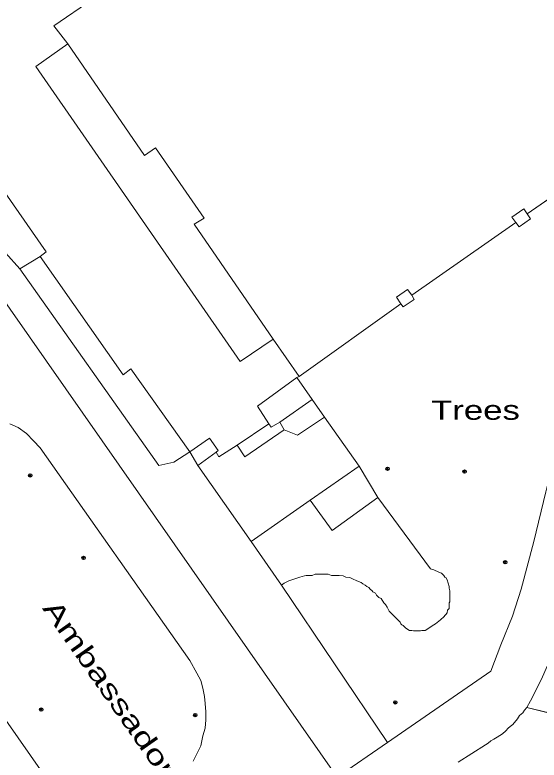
# Model space of a CAD drawing. Extents: x 528790 to 529292, y 179350 to 179856.
# Drawn here: x 529081.7 to 529129.4, y 179559 to 179626.8 of the extents above; entities that cross this region are included whole.
import ezdxf

# ---------------------------------------------------------------- set-up
doc = ezdxf.new("R2010")
doc.units = 0
doc.header["$LTSCALE"] = 0.6
doc.header["$PDMODE"] = 32
doc.header["$PDSIZE"] = 0.3
doc.layers.add('1', color=7, linetype='Continuous', lineweight=13)
doc.layers.add('2', color=7, linetype='Continuous', lineweight=13)
doc.layers.add('3', color=7, linetype='Continuous')
doc.layers.add('5', color=7, linetype='Continuous')

msp = doc.modelspace()

# ---------------------------------------------------------------- linework, layer by layer
at = {"layer": '1'}
for points in [[(529079.55, 179612.4), (529084.55, 179605.25), (529084, 179604.8), (529091.55, 179594.05), (529092.25, 179594.6), (529097.6, 179587.05), (529099.4, 179588.3), (529100.2, 179587.15), (529100, 179587), (529100.25, 179586.6), (529101.9, 179587.65), (529104.8, 179589.6), (529103.75, 179591.2), (529107.35, 179593.8), (529107.55, 179593.9), (529105.2, 179597.3), (529102.2, 179595.25), (529083.6, 179622.1), (529086.5, 179624.15), (529085.25, 179625.8), (529088.8, 179628.25)], [(529088.8, 179628.25), (529085.25, 179625.8), (529086.5, 179624.15), (529093.5, 179614), (529094.5, 179614.7), (529098.9, 179608.3), (529098, 179607.75), (529105.2, 179597.3), (529107.55, 179593.9), (529116.8, 179600.5), (529116.4, 179601.1)], [(529137.65, 179615.2), (529128.3, 179608.7), (529128.6, 179608.25), (529127.55, 179607.5), (529127.25, 179607.9), (529117.8, 179601.3), (529118, 179600.9), (529117, 179600.25), (529116.8, 179600.5), (529107.55, 179593.9), (529107.35, 179593.8), (529108.75, 179591.8), (529109.85, 179590.2), (529113, 179585.75), (529114.7, 179582.9), (529119.5, 179576.4), (529119.8, 179576.3), (529120.25, 179576.1), (529120.5, 179576), (529120.7, 179575.8), (529120.8, 179575.65), (529120.9, 179575.6), (529121, 179575.4), (529121.2, 179574.8), (529121.2, 179574.65), (529121.25, 179574.4), (529121.25, 179573.4), (529121.2, 179573.3), (529121.2, 179572.8), (529121.05, 179572.65), (529121, 179572.4), (529120.9, 179572.25), (529120.8, 179572.15), (529120.75, 179572.05), (529120.4, 179571.75), (529120.25, 179571.65), (529119.95, 179571.4), (529119.8, 179571.3), (529119, 179570.8), (529118.7, 179570.8), (529118.6, 179570.75), (529117.95, 179570.75), (529117.8, 179570.8), (529117.6, 179570.8), (529117.25, 179571), (529117, 179571.25), (529116.9, 179571.3), (529116.8, 179571.4), (529116.75, 179571.55), (529115.75, 179572.55), (529115.55, 179572.9), (529115.4, 179573.15), (529115.25, 179573.3), (529115, 179573.7), (529114.8, 179573.8), (529114.6, 179574), (529114.5, 179574.2), (529114.25, 179574.3), (529114.2, 179574.4), (529114, 179574.55), (529113.9, 179574.7), (529113.7, 179574.8), (529113.55, 179574.9), (529113.35, 179575.05), (529113.2, 179575.15), (529112.8, 179575.3), (529112.4, 179575.5), (529112.15, 179575.6), (529111.8, 179575.65), (529111.55, 179575.75), (529111.2, 179575.8), (529110.5, 179575.8), (529110.2, 179575.9), (529109, 179575.9), (529108.75, 179575.8), (529108.2, 179575.8), (529108.05, 179575.75), (529107.6, 179575.65), (529107.35, 179575.55), (529107.15, 179575.5), (529106.6, 179575.3), (529106.2, 179575.1), (529105.95, 179574.9), (529115.6, 179560.6), (529125, 179567.1), (529125.9, 179569.5), (529126.95, 179572.1), (529127.75, 179574.55), (529128.9, 179578.9), (529130, 179583.4)], [(529127.25, 179607.9), (529126.9, 179608.4), (529128, 179609.15), (529128.3, 179608.7), (529137.65, 179615.2)], [(529116.4, 179601.1), (529117.4, 179601.8), (529117.8, 179601.3), (529127.25, 179607.9)], [(529079.7, 179602.25), (529111, 179557.45), (529115.6, 179560.6), (529105.95, 179574.9), (529103.2, 179578.9), (529098.35, 179585.8), (529097.6, 179587.05), (529096.15, 179586.1), (529094.8, 179585.8), (529082.15, 179603.7), (529079.5, 179606.6)], [(529111, 179557.45), (529079.7, 179602.25)], [(529097.9, 179558.9), (529098.6, 179560.3), (529098.8, 179561.2), (529099, 179561.9), (529099.05, 179562.65), (529099.05, 179563.4), (529099, 179564.15), (529098.95, 179564.8), (529098.8, 179565.55), (529098.6, 179566.25), (529098.25, 179566.9), (529097.6, 179568.05), (529084, 179587.4), (529083.4, 179588.05), (529082.75, 179588.7), (529082, 179589.25), (529081.25, 179589.6)], [(529081.25, 179589.6), (529082, 179589.25), (529082.75, 179588.7), (529083.4, 179588.05), (529084, 179587.4), (529097.6, 179568.05), (529098.25, 179566.9), (529098.6, 179566.25), (529098.8, 179565.55), (529098.95, 179564.8), (529099, 179564.15), (529099.05, 179563.4), (529099.05, 179562.65), (529099, 179561.9), (529098.8, 179561.2), (529098.6, 179560.3), (529097.9, 179558.9)], [(529130, 179583.4), (529128.9, 179578.9), (529127.75, 179574.55), (529126.95, 179572.1), (529125.9, 179569.5), (529125, 179567.1), (529115.6, 179560.6), (529111, 179557.45)], [(529069.4, 179579), (529084.25, 179557.8)], [(529084.25, 179557.8), (529069.4, 179579)], [(529122, 179558.8), (529124.5, 179560.4), (529124.75, 179560.55), (529125, 179560.75), (529125.25, 179560.9), (529125.55, 179561.1), (529126.05, 179561.4), (529126.35, 179561.65), (529126.55, 179561.9), (529126.75, 179562.05), (529127, 179562.25), (529127.4, 179562.75), (529127.6, 179563.05), (529127.9, 179563.3), (529128.05, 179563.55), (529128.25, 179563.8), (529128.6, 179564.4), (529129.55, 179566.3)], [(529129.55, 179566.3), (529128.6, 179564.4), (529128.25, 179563.8), (529139.05, 179561.1)], [(529139.05, 179561.1), (529128.25, 179563.8), (529128.05, 179563.55), (529127.9, 179563.3), (529127.6, 179563.05), (529127.4, 179562.75), (529127, 179562.25), (529126.75, 179562.05), (529126.55, 179561.9), (529126.35, 179561.65), (529126.05, 179561.4), (529125.55, 179561.1), (529125.25, 179560.9), (529125, 179560.75), (529124.75, 179560.55), (529124.5, 179560.4), (529122, 179558.8)]]:
    msp.add_lwpolyline(points, dxfattribs=at)
for points in [[(529086.5, 179624.15), (529083.6, 179622.1), (529102.2, 179595.25), (529105.2, 179597.3), (529098, 179607.75), (529098.9, 179608.3), (529094.5, 179614.7), (529093.5, 179614)], [(529084, 179604.8), (529084.55, 179605.25), (529079.55, 179612.4), (529070.45, 179606.1), (529070.8, 179605.55), (529071, 179605.3), (529071.4, 179605), (529071.6, 179604.9), (529071.8, 179604.9), (529072, 179605.05), (529072.2, 179605.15), (529072.9, 179605.65), (529073.55, 179606.05), (529074.2, 179606.4), (529074.8, 179606.65), (529075.4, 179606.8), (529075.95, 179607), (529077.15, 179607.1), (529077.8, 179607.05), (529078.4, 179606.9), (529078.95, 179606.8), (529079.5, 179606.6), (529082.15, 179603.7)], [(529128.3, 179608.7), (529128, 179609.15), (529126.9, 179608.4), (529127.25, 179607.9), (529127.55, 179607.5), (529128.6, 179608.25)], [(529082.15, 179603.7), (529094.8, 179585.8), (529096.15, 179586.1), (529097.6, 179587.05), (529092.25, 179594.6), (529091.55, 179594.05), (529084, 179604.8)], [(529117.8, 179601.3), (529117.4, 179601.8), (529116.4, 179601.1), (529116.8, 179600.5), (529117, 179600.25), (529118, 179600.9)], [(529104.8, 179589.6), (529105, 179589.3), (529105.8, 179589.75), (529108.75, 179591.8), (529107.35, 179593.8), (529103.75, 179591.2)], [(529108.75, 179591.8), (529105.8, 179589.75), (529106.2, 179589.05), (529107.4, 179588.55), (529109.85, 179590.2)], [(529100, 179587), (529098.35, 179585.8), (529103.2, 179578.9), (529108.55, 179582.65), (529113, 179585.75), (529109.85, 179590.2), (529107.4, 179588.55), (529106.2, 179589.05), (529102.6, 179586.6), (529101.9, 179587.65), (529100.25, 179586.6)], [(529101.9, 179587.65), (529102.6, 179586.6), (529106.2, 179589.05), (529105.8, 179589.75), (529105, 179589.3), (529104.8, 179589.6)], [(529098.35, 179585.8), (529100, 179587), (529100.2, 179587.15), (529099.4, 179588.3), (529097.6, 179587.05)], [(529113, 179585.75), (529108.55, 179582.65), (529110.55, 179579.9), (529114.7, 179582.9)], [(529108.55, 179582.65), (529103.2, 179578.9), (529105.95, 179574.9), (529106.2, 179575.1), (529106.6, 179575.3), (529107.15, 179575.5), (529107.35, 179575.55), (529107.6, 179575.65), (529108.05, 179575.75), (529108.2, 179575.8), (529108.75, 179575.8), (529109, 179575.9), (529110.2, 179575.9), (529110.5, 179575.8), (529111.2, 179575.8), (529111.55, 179575.75), (529111.8, 179575.65), (529112.15, 179575.6), (529112.4, 179575.5), (529112.8, 179575.3), (529113.2, 179575.15), (529113.35, 179575.05), (529113.55, 179574.9), (529113.7, 179574.8), (529113.9, 179574.7), (529114, 179574.55), (529114.2, 179574.4), (529114.25, 179574.3), (529114.5, 179574.2), (529114.6, 179574), (529114.8, 179573.8), (529115, 179573.7), (529115.25, 179573.3), (529115.4, 179573.15), (529115.55, 179572.9), (529115.75, 179572.55), (529116.75, 179571.55), (529116.8, 179571.4), (529116.9, 179571.3), (529117, 179571.25), (529117.25, 179571), (529117.6, 179570.8), (529117.8, 179570.8), (529117.95, 179570.75), (529118.6, 179570.75), (529118.7, 179570.8), (529119, 179570.8), (529119.8, 179571.3), (529119.95, 179571.4), (529120.25, 179571.65), (529120.4, 179571.75), (529120.75, 179572.05), (529120.8, 179572.15), (529120.9, 179572.25), (529121, 179572.4), (529121.05, 179572.65), (529121.2, 179572.8), (529121.2, 179573.3), (529121.25, 179573.4), (529121.25, 179574.4), (529121.2, 179574.65), (529121.2, 179574.8), (529121, 179575.4), (529120.9, 179575.6), (529120.8, 179575.65), (529120.7, 179575.8), (529120.5, 179576), (529120.25, 179576.1), (529119.8, 179576.3), (529119.5, 179576.4), (529114.7, 179582.9), (529110.55, 179579.9)]]:
    msp.add_lwpolyline(points, close=True, dxfattribs=at)
at = {"layer": '2'}
for p, q in [((529137.65, 179615.2), (529128.3, 179608.7)), ((529127.25, 179607.9), (529117.8, 179601.3)), ((529082.15, 179603.7), (529084, 179604.8)), ((529116.8, 179600.5), (529107.55, 179593.9)), ((529105.2, 179597.3), (529107.55, 179593.9)), ((529107.55, 179593.9), (529107.35, 179593.8)), ((529107.35, 179593.8), (529108.75, 179591.8)), ((529105.8, 179589.75), (529108.75, 179591.8)), ((529108.75, 179591.8), (529109.85, 179590.2)), ((529109.85, 179590.2), (529113, 179585.75)), ((529101.9, 179587.65), (529104.8, 179589.6)), ((529105.8, 179589.75), (529106.2, 179589.05)), ((529098.35, 179585.8), (529097.6, 179587.05)), ((529098.35, 179585.8), (529100, 179587)), ((529103.2, 179578.9), (529098.35, 179585.8)), ((529113, 179585.75), (529108.55, 179582.65)), ((529113, 179585.75), (529114.7, 179582.9)), ((529108.55, 179582.65), (529103.2, 179578.9)), ((529114.7, 179582.9), (529119.5, 179576.4)), ((529105.95, 179574.9), (529103.2, 179578.9)), ((529115.6, 179560.6), (529105.95, 179574.9)), ((529139.05, 179561.1), (529128.25, 179563.8)), ((529115.6, 179560.6), (529111, 179557.45))]:
    msp.add_line(p, q, dxfattribs=at)
for points in [[(529095.8, 179649.8), (529097, 179650.65), (529099.6, 179646.9), (529100.4, 179647.5), (529103.2, 179643.4), (529102.5, 179642.8), (529104.9, 179639.3), (529099.6, 179635.65), (529099.6, 179635.15), (529089.35, 179628.05), (529088.8, 179628.25), (529085.25, 179625.8), (529086.5, 179624.15)], [(529086.5, 179624.15), (529083.6, 179622.1), (529102.2, 179595.25), (529105.2, 179597.3)], [(529086.5, 179624.15), (529093.5, 179614), (529094.5, 179614.7), (529098.9, 179608.3), (529098, 179607.75), (529105.2, 179597.3)], [(529084, 179604.8), (529084.55, 179605.25), (529079.55, 179612.4), (529070.45, 179606.1)], [(529127.25, 179607.9), (529126.9, 179608.4), (529128, 179609.15), (529128.3, 179608.7)], [(529128.3, 179608.7), (529128.6, 179608.25), (529127.55, 179607.5), (529127.25, 179607.9)], [(529070.45, 179606.1), (529070.8, 179605.55), (529071, 179605.3), (529071.4, 179605), (529071.6, 179604.9), (529071.8, 179604.9), (529072, 179605.05), (529072.2, 179605.15), (529072.9, 179605.65), (529073.55, 179606.05), (529074.2, 179606.4), (529074.8, 179606.65), (529075.4, 179606.8), (529075.95, 179607), (529077.15, 179607.1), (529077.8, 179607.05), (529078.4, 179606.9), (529078.95, 179606.8), (529079.5, 179606.6), (529082.15, 179603.7)], [(529097.6, 179587.05), (529092.25, 179594.6), (529091.55, 179594.05), (529084, 179604.8)], [(529111, 179557.45), (529079.7, 179602.25), (529079.05, 179603.05), (529078.75, 179603.3), (529078.25, 179603.65), (529077.5, 179604.05), (529077.05, 179604.15), (529076.6, 179604.2), (529076.15, 179604.15), (529075.75, 179604.05), (529074.95, 179603.75), (529074.6, 179603.5), (529074.25, 179603.2), (529070.75, 179600.75), (529070.4, 179600.6), (529070, 179600.4), (529069.8, 179600.4), (529069.55, 179600.55)], [(529097.6, 179587.05), (529096.15, 179586.1), (529094.8, 179585.8), (529082.15, 179603.7)], [(529116.8, 179600.5), (529116.4, 179601.1), (529117.4, 179601.8), (529117.8, 179601.3)], [(529117.8, 179601.3), (529118, 179600.9), (529117, 179600.25), (529116.8, 179600.5)], [(529104.8, 179589.6), (529103.75, 179591.2), (529107.35, 179593.8)], [(529106.2, 179589.05), (529107.4, 179588.55), (529109.85, 179590.2)], [(529081.25, 179589.6), (529082, 179589.25), (529082.75, 179588.7), (529083.4, 179588.05), (529084, 179587.4), (529097.6, 179568.05), (529098.25, 179566.9), (529098.6, 179566.25), (529098.8, 179565.55), (529098.95, 179564.8), (529099, 179564.15), (529099.05, 179563.4), (529099.05, 179562.65), (529099, 179561.9), (529098.8, 179561.2), (529098.6, 179560.3), (529097.9, 179558.9)], [(529104.8, 179589.6), (529105, 179589.3), (529105.8, 179589.75)], [(529106.2, 179589.05), (529102.6, 179586.6), (529101.9, 179587.65)], [(529100, 179587), (529100.2, 179587.15), (529099.4, 179588.3), (529097.6, 179587.05)], [(529101.9, 179587.65), (529100.25, 179586.6), (529100, 179587)], [(529131, 179587.4), (529130, 179583.4), (529128.9, 179578.9), (529127.75, 179574.55), (529126.95, 179572.1), (529125.9, 179569.5), (529125, 179567.1), (529115.6, 179560.6)], [(529136.2, 179587.3), (529132.4, 179573.1), (529131, 179569.6), (529130.15, 179567.6), (529129.55, 179566.3), (529128.6, 179564.4), (529128.25, 179563.8)], [(529114.7, 179582.9), (529110.55, 179579.9), (529108.55, 179582.65)], [(529084.25, 179557.8), (529069.4, 179579)], [(529105.95, 179574.9), (529106.2, 179575.1), (529106.6, 179575.3), (529107.15, 179575.5), (529107.35, 179575.55), (529107.6, 179575.65), (529108.05, 179575.75), (529108.2, 179575.8), (529108.75, 179575.8), (529109, 179575.9), (529110.2, 179575.9), (529110.5, 179575.8), (529111.2, 179575.8), (529111.55, 179575.75), (529111.8, 179575.65), (529112.15, 179575.6), (529112.4, 179575.5), (529112.8, 179575.3), (529113.2, 179575.15), (529113.35, 179575.05), (529113.55, 179574.9), (529113.7, 179574.8), (529113.9, 179574.7), (529114, 179574.55), (529114.2, 179574.4), (529114.25, 179574.3), (529114.5, 179574.2), (529114.6, 179574), (529114.8, 179573.8), (529115, 179573.7), (529115.25, 179573.3), (529115.4, 179573.15), (529115.55, 179572.9), (529115.75, 179572.55), (529116.75, 179571.55), (529116.8, 179571.4), (529116.9, 179571.3), (529117, 179571.25), (529117.25, 179571), (529117.6, 179570.8), (529117.8, 179570.8), (529117.95, 179570.75), (529118.6, 179570.75), (529118.7, 179570.8), (529119, 179570.8), (529119.8, 179571.3), (529119.95, 179571.4), (529120.25, 179571.65), (529120.4, 179571.75), (529120.75, 179572.05), (529120.8, 179572.15), (529120.9, 179572.25), (529121, 179572.4), (529121.05, 179572.65), (529121.2, 179572.8), (529121.2, 179573.3), (529121.25, 179573.4), (529121.25, 179574.4), (529121.2, 179574.65), (529121.2, 179574.8), (529121, 179575.4), (529120.9, 179575.6), (529120.8, 179575.65), (529120.7, 179575.8), (529120.5, 179576), (529120.25, 179576.1), (529119.8, 179576.3), (529119.5, 179576.4)], [(529128.25, 179563.8), (529128.05, 179563.55), (529127.9, 179563.3), (529127.6, 179563.05), (529127.4, 179562.75), (529127, 179562.25), (529126.75, 179562.05), (529126.55, 179561.9), (529126.35, 179561.65), (529126.05, 179561.4), (529125.55, 179561.1), (529125.25, 179560.9), (529125, 179560.75), (529124.75, 179560.55), (529124.5, 179560.4), (529122, 179558.8)]]:
    msp.add_lwpolyline(points, dxfattribs=at)
at = {"layer": '3'}
for p in [(529083.1, 179584.9), (529115.6, 179585.5), (529122.6, 179585.25), (529087.95, 179577.4), (529126.3, 179577), (529116.3, 179564.25), (529084.1, 179563.6), (529098.1, 179563.1)]:
    msp.add_point(p, dxfattribs=at)

# ---------------------------------------------------------------- texts
at = {"layer": '5', "width": 1.35}
msp.add_text('Trees', height=1.75, dxfattribs=at).set_placement((529119.55, 179589.96))
at = {"layer": '5', "width": 1.45}
msp.add_text("Ambassadors' Court", height=1.75, rotation=305, dxfattribs=at).set_placement((529084.15, 179572.8))

doc.saveas('drawing.dxf')
